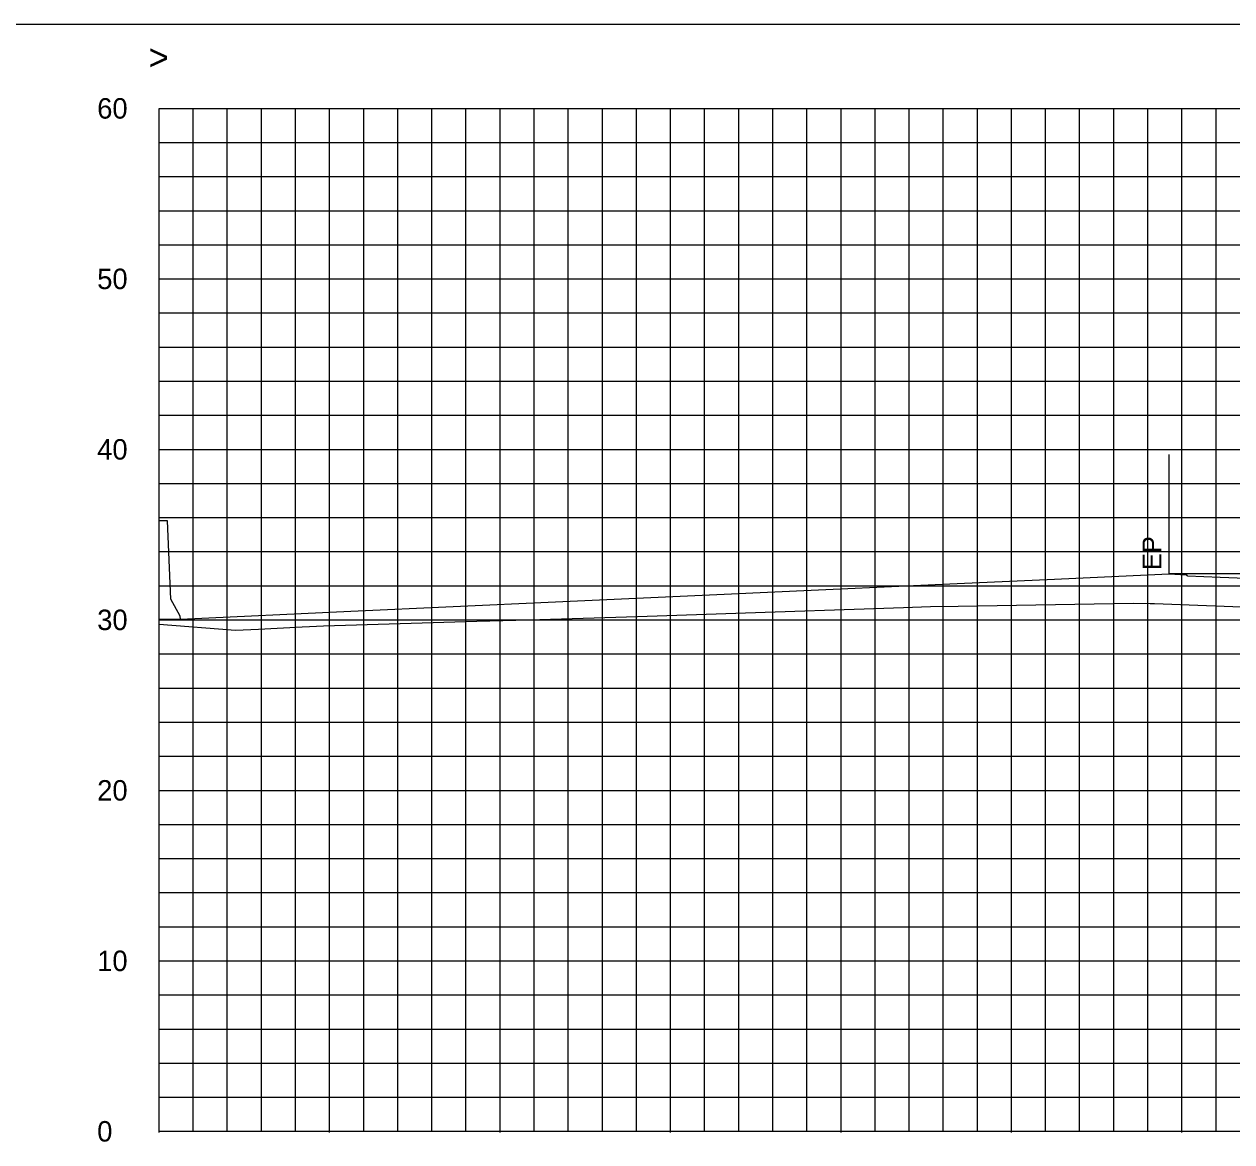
# Model space of a CAD drawing. Extents: x 1797809 to 2198143, y 249608 to 1237864.
# Drawn here: x 2195380.9 to 2195451.7, y 1237162.5 to 1237228 of the extents above; entities that cross this region are included whole.
import ezdxf

# ---------------------------------------------------------------- set-up
doc = ezdxf.new("R2010")
doc.units = 0
for name, color, linetype in [('3', 7, 'Continuous'), ('31', 7, 'Continuous'), ('60', 7, 'Continuous'), ('Default', 7, 'Continuous'), ('DESIGN - SHEET - Light Grid', 7, 'Continuous'), ('DESIGN - TRAFFIC CONTROL PERMANENT - Signs', 7, 'Continuous'), ('GSDIMS', 7, 'Continuous'), ('GSSHT', 7, 'Continuous'), ('Level 55', 7, 'Continuous')]:
    doc.layers.add(name, color=color, linetype=linetype)

msp = doc.modelspace()

# ---------------------------------------------------------------- linework, layer by layer
at = {"layer": '3'}
for p, q in [((2195228.783, 1237228.046), (2195528.783, 1237228.046)), ((2195448.033, 1237195.8), (2195448.033, 1237202.8))]:
    msp.add_line(p, q, dxfattribs=at)
at = {"layer": '60'}
for p, q in [((2195388.783, 1237163.106), (2195388.783, 1237223.106)), ((2195388.783, 1237163.046), (2195388.783, 1237163.106)), ((2195388.783, 1237163.106), (2195518.783, 1237163.106)), ((2195398.783, 1237163.046), (2195398.783, 1237163.106)), ((2195408.783, 1237163.046), (2195408.783, 1237163.106)), ((2195418.783, 1237163.046), (2195418.783, 1237163.106)), ((2195428.783, 1237163.046), (2195428.783, 1237163.106)), ((2195438.783, 1237163.046), (2195438.783, 1237163.106)), ((2195448.783, 1237163.046), (2195448.783, 1237163.106))]:
    msp.add_line(p, q, dxfattribs=at)
at = {"layer": 'Default'}
msp.add_lwpolyline([(2195388.783, 1237193.149), (2195390.033, 1237193.149), (2195390.014, 1237193.319), (2195389.463, 1237194.319), (2195389.283, 1237198.906), (2195388.783, 1237198.906)], dxfattribs=at)
at = {"layer": 'DESIGN - SHEET - Light Grid'}
msp.add_lwpolyline([(2195388.783, 1237192.848), (2195393.265, 1237192.507), (2195394.616, 1237192.569), (2195397.175, 1237192.694), (2195397.611, 1237192.711), (2195398.426, 1237192.75), (2195407.416, 1237193.023), (2195410.473, 1237193.115), (2195416.845, 1237193.31), (2195422.03, 1237193.474), (2195432.448, 1237193.839), (2195434.033, 1237193.89), (2195435.65, 1237193.918), (2195445.928, 1237194.08), (2195446.918, 1237194.064), (2195447.18, 1237194.058), (2195453.801, 1237193.813)], dxfattribs=at)
at = {"layer": 'DESIGN - TRAFFIC CONTROL PERMANENT - Signs'}
msp.add_lwpolyline([(2195388.783, 1237193.149), (2195390.033, 1237193.149), (2195400.033, 1237193.606), (2195412.033, 1237194.155), (2195421.934, 1237194.607), (2195424.033, 1237194.703), (2195436.033, 1237195.252), (2195440.873, 1237195.473), (2195448.033, 1237195.8), (2195448.695, 1237195.774), (2195449.03, 1237195.76), (2195449.078, 1237195.712), (2195449.103, 1237195.687), (2195451.031, 1237195.61), (2195458.033, 1237195.33), (2195459.468, 1237195.273), (2195463.533, 1237195.11), (2195482.204, 1237190.443)], dxfattribs=at)
at = {"layer": 'GSDIMS'}
msp.add_line((2195460.845, 1237195.8), (2195448.033, 1237195.8), dxfattribs=at)
at = {"layer": 'GSSHT'}
for p, q in [((2195388.783, 1237223.106), (2195518.783, 1237223.106)), ((2195390.783, 1237163.106), (2195390.783, 1237223.106)), ((2195392.783, 1237163.106), (2195392.783, 1237223.106)), ((2195394.783, 1237163.106), (2195394.783, 1237223.106)), ((2195396.783, 1237163.106), (2195396.783, 1237223.106)), ((2195398.783, 1237163.106), (2195398.783, 1237223.106)), ((2195400.783, 1237163.106), (2195400.783, 1237223.106)), ((2195402.783, 1237163.106), (2195402.783, 1237223.106)), ((2195404.783, 1237163.106), (2195404.783, 1237223.106)), ((2195406.783, 1237163.106), (2195406.783, 1237223.106)), ((2195408.783, 1237163.106), (2195408.783, 1237223.106)), ((2195410.783, 1237163.106), (2195410.783, 1237223.106)), ((2195412.783, 1237163.106), (2195412.783, 1237223.106)), ((2195414.783, 1237163.106), (2195414.783, 1237223.106)), ((2195416.783, 1237163.106), (2195416.783, 1237223.106)), ((2195418.783, 1237163.106), (2195418.783, 1237223.106)), ((2195420.783, 1237163.106), (2195420.783, 1237223.106)), ((2195422.783, 1237163.106), (2195422.783, 1237223.106)), ((2195424.783, 1237163.106), (2195424.783, 1237223.106)), ((2195426.783, 1237163.106), (2195426.783, 1237223.106)), ((2195428.783, 1237163.106), (2195428.783, 1237223.106)), ((2195430.783, 1237163.106), (2195430.783, 1237223.106)), ((2195432.783, 1237163.106), (2195432.783, 1237223.106)), ((2195434.783, 1237163.106), (2195434.783, 1237223.106)), ((2195436.783, 1237163.106), (2195436.783, 1237223.106)), ((2195438.783, 1237163.106), (2195438.783, 1237223.106)), ((2195440.783, 1237163.106), (2195440.783, 1237223.106)), ((2195442.783, 1237163.106), (2195442.783, 1237223.106)), ((2195444.783, 1237163.106), (2195444.783, 1237223.106)), ((2195446.783, 1237163.106), (2195446.783, 1237223.106)), ((2195448.783, 1237163.106), (2195448.783, 1237223.106)), ((2195450.783, 1237163.106), (2195450.783, 1237223.106)), ((2195388.783, 1237221.106), (2195518.783, 1237221.106)), ((2195388.783, 1237219.106), (2195518.783, 1237219.106)), ((2195388.783, 1237217.106), (2195518.783, 1237217.106)), ((2195388.783, 1237215.106), (2195518.783, 1237215.106)), ((2195388.783, 1237213.106), (2195518.783, 1237213.106)), ((2195388.783, 1237211.106), (2195518.783, 1237211.106)), ((2195388.783, 1237209.106), (2195518.783, 1237209.106)), ((2195388.783, 1237207.106), (2195518.783, 1237207.106)), ((2195388.783, 1237205.106), (2195518.783, 1237205.106)), ((2195388.783, 1237203.106), (2195518.783, 1237203.106)), ((2195388.783, 1237201.106), (2195518.783, 1237201.106)), ((2195388.783, 1237199.106), (2195518.783, 1237199.106)), ((2195388.783, 1237197.106), (2195518.783, 1237197.106)), ((2195388.783, 1237195.106), (2195518.783, 1237195.106)), ((2195388.783, 1237193.106), (2195518.783, 1237193.106)), ((2195388.783, 1237191.106), (2195518.783, 1237191.106)), ((2195388.783, 1237189.106), (2195518.783, 1237189.106)), ((2195388.783, 1237187.106), (2195518.783, 1237187.106)), ((2195388.783, 1237185.106), (2195518.783, 1237185.106)), ((2195388.783, 1237183.106), (2195518.783, 1237183.106)), ((2195388.783, 1237181.106), (2195518.783, 1237181.106)), ((2195388.783, 1237179.106), (2195518.783, 1237179.106)), ((2195388.783, 1237177.106), (2195518.783, 1237177.106)), ((2195388.783, 1237175.106), (2195518.783, 1237175.106)), ((2195388.783, 1237173.106), (2195518.783, 1237173.106)), ((2195388.783, 1237171.106), (2195518.783, 1237171.106)), ((2195388.783, 1237169.106), (2195518.783, 1237169.106)), ((2195388.783, 1237167.106), (2195518.783, 1237167.106)), ((2195388.783, 1237165.106), (2195518.783, 1237165.106)), ((2195388.783, 1237163.106), (2195518.783, 1237163.106))]:
    msp.add_line(p, q, dxfattribs=at)

# ---------------------------------------------------------------- texts
at = {"layer": '31'}
for s, p in [('60', (2195385.15, 1237222.506)), ('50', (2195385.15, 1237212.506)), ('40', (2195385.15, 1237202.506)), ('30', (2195385.15, 1237192.506)), ('20', (2195385.15, 1237182.506)), ('10', (2195385.15, 1237172.506)), ('0', (2195385.15, 1237162.506))]:
    msp.add_text(s, height=1.2, dxfattribs=at).set_placement(p)
at = {"layer": '60'}
msp.add_text('>', height=1.5, dxfattribs=at).set_placement((2195388.175, 1237225.356))
at = {"layer": 'Level 55'}
msp.add_text('EP', height=1.1105, rotation=90, dxfattribs=at).set_placement((2195447.581, 1237196.032))

doc.saveas('drawing.dxf')
